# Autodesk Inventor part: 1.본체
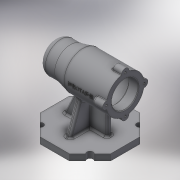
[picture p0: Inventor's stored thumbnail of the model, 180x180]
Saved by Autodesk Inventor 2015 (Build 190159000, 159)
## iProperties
Created: 2019-12
Part Number: 1.본체
Material: 일반
Document SubType Name: Modeling
Designer: SCD-A02
Density: 1 g/cm^3
Appearance: 기본값
Author: SCD-A02
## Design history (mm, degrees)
sketch "스케치1"
  geometry: L1 (0, 0)-(0, 25); L2 (0, 25)-(25, 25); L3 (25, 25)-(45, 30); L4 (45, 30)-(112, 30); L5 (112, 30)-(112, 0); L6 (112, 0)-(0, 0)
  constraints: 12 end point, 2 perpendicular, 2 vertical, 1 parallel
  dimensions: "d0" = 50 diameter of L2 L6; "d1" = 60 diameter of L4 L6; "d2" = 25 distance of L1.end L2.end; "d3" = 45 horizontal distance of L1.end L3.end; "d4" = 112 distance between parallel lines of L1 L5
revolve "회전1" sketch "스케치1" stored, may be unused: angle "d5" = 90 deg
sketch "스케치2"
  geometry: L1 (6, 0)-(9, 0); L2 (9, 0)-(9, 10.5); L3 (9, 10.5)-(6, 10.5); L4 (6, 10.5)-(6, 0); L5 (9, 0)-(13, 0); L6 (13, 0)-(13, 16); L7 (13, 16)-(9, 16); L8 (9, 16)-(9, 0); L9 (13, 0)-(31, 0); L10 (31, 0)-(31, 17.5); L11 (31, 17.5)-(13, 17.5); L12 (13, 17.5)-(13, 0); L13 (31, 0)-(43, 0); L14 (43, 0)-(43, 21); L15 (43, 21)-(31, 21); L16 (31, 21)-(31, 0); L17 (43, 0)-(97, 0); L18 (97, 0)-(97, 24); L19 (97, 24)-(43, 24); L20 (43, 24)-(43, 0); L21 (112, -30)-(112, 30) reference; L22 (97, 0)-(112, 0); L23 (112, 0)-(112, 21); L24 (112, 21)-(97, 21); L25 (97, 21)-(97, 0); 1 further point
  constraints: 48 end point, 12 parallel, 6 horizontal, 6 perpendicular, 1 point on line
  dimensions: "d6" = 0 vertical distance of point (0, 0) L1.start; "d7" = 3 distance of L2.end L3.end; "d8" = 4 distance of L6.end L7.end; "d9" = 18 distance of L10.end L11.end; "d10" = 12 distance of L14.end L15.end; "d11" = 42 diameter of L15 L13; "d12" = 48 diameter of L19 L17; "d13" = 15 distance between parallel lines of L23 L25; "d14" = 54 distance between parallel lines of L25 L14; "d15" = 42 diameter of L24 L22; "d16" = 35 diameter of L11 L9; "d17" = 21 diameter of L3 L1; "d18" = 32 diameter of L7 L5
revolve "회전2" stored, may be unused: angle "d19" = 90 deg
node "작업 평면1"
sketch "스케치3"
  geometry: L1 (56, 0)-(5.263, 50.737); L2 (56, 0)-(0, 0); L3 (16.402, 39.598)-(0, 23.196); L4 (0, 23.196)-(16.402, 39.598); L5 (16.402, 39.598)-(32.804, 56); L6 (56, 56)-(32.804, 56); L7 (0, 0)-(0, 23.196); L8 (56, 0)-(95.901, 39.901); L9 (112, 0)-(112, 23.196); L10 (56, 56)-(79.196, 56); L11 (95.598, 39.598)-(79.196, 56); L12 (95.598, 39.598)-(112, 23.196); L13 (0, 0)-(0, -23.196); L14 (16.402, -39.598)-(0, -23.196); L15 (16.402, -39.598)-(32.804, -56); L16 (56, -56)-(32.804, -56); L17 (56, -56)-(79.196, -56); L18 (95.598, -39.598)-(79.196, -56); L19 (95.598, -39.598)-(112, -23.196); L20 (112, 0)-(112, -23.196); A1 r 56 centre (56, 0) between (16.402, 39.598) and (0, 0)
  constraints: 40 end point, 7 symmetric about line, 6 tangent, 3 horizontal, 3 point on line, 2 perpendicular, 2 point on circle, 2 vertical, 1 centre point, 1 collinear
  dimensions: "d21" = 56 distance of L1.start L2.end; "d22" = 112 diameter of A1; "d23" = 45 deg angle of L1 L2; "d24" = 45 deg angle of L8 L2
extrude "돌출1" join sketch "스케치3" distance "d25" = 10; taper "d26" = 0 deg
sketch "스케치4"
  geometry: L1 (-32.804, -70)-(0, -70) reference; L2 (-18, -70)-(-40.099, -22.609); L3 (-40.099, -22.609)-(-87, -22.609); L4 (-112, -70)-(-79.196, -70) reference; L5 (-79.196, -70)-(-32.804, -70) reference; L6 (0, -80)-(0, -70) reference; L7 (-87, -22.609)-(-87, -70); L8 (-18, -70)-(-87, -70); L9 (-112, -80)-(-112, -70) reference; 1 further point
  constraints: 8 end point, 1 collinear, 1 horizontal, 1 point on line, 1 vertical
  dimensions: "d27" = 18 distance from line of L2.start L6; "d28" = 25 distance between parallel lines of L7 L9; "d62" = 115 deg angle of L2 L1
extrude "돌출2" join sketch "스케치4" stored distance "d29" = 8; taper "d30" = 0 deg
node "작업 평면2"
sketch "스케치5"
  geometry: L1 (70, -36)-(0, -10.522); L2 (0, -10.522)-(0, 0); L3 (0, 0)-(70, 0); L4 (27.875, -4)-(70, -4) reference; L5 (70, 0)-(70, -36); L6 (70, -56)-(70, -23.196) reference; L7 (80, -56)-(70, -56) reference; L8 (70, 36)-(0, 10.522); L9 (0, 10.522)-(0, 0); L10 (27.875, 4)-(70, 4); L11 (70, 0)-(70, 36); 1 further point
  constraints: 16 end point, 5 symmetric about line, 1 parallel, 1 perpendicular, 1 vertical
  dimensions: "d32" = 0 distance between parallel lines of L5 L6; "d33" = 20 distance from line of L1.start L7; "d34" = 110 deg angle of L1 L6
extrude "돌출3" join sketch "스케치5" stored distance "d35" = 8; taper "d36" = 0 deg
revolve "회전3" stored, may be unused: angle "d37" = 90 deg
sketch "스케치6"
  geometry: C1 r 21 at (0, 0) reference; C2 r 6 at (-30, 0); A1 r 30 centre (0, 0) between (29.732, 4) and (29.732, -4) reference; A2 r 30 centre (0, 0) between (29.732, 4) and (29.732, -4) reference
  constraints: 2 point on circle, 1 centre point, 1 horizontal alignment
  dimensions: "d38" = 12 diameter of C2
extrude "돌출4" join sketch "스케치6" distance "d39" = 16; taper "d40" = 0 deg
fillet "모깎기1" dims "d41" = 3
fillet "모깎기2" dims "d42" = 1
sketch "스케치7"
  geometry: A1 r 6 centre (0, 0) between (-0.171, 5.998) and (-0.171, -5.998) reference
hole "구멍1" sketch "스케치7" at (0, 0) diameter "d43" = 3.242; stored, may be unused: countersink angle "d47" = 90 deg, drill point angle "d49" = 118 deg; dims "d44" = 8, "d45" = 4, "d46" = 2, "d48" = 11
sketch "스케치8"
  geometry: L1 (32.804, 56)-(0, 23.196) reference; C1 r 5 at (16.402, 39.598); 1 further point
  constraints: 1 centre point, 1 midpoint
  dimensions: "d53" = 10 diameter of C1
extrude "돌출5" cut sketch "스케치8" stored distance "d54" = 16; taper "d55" = 0 deg
fillet "모깎기3" dims "d56" = 10, "d57" = 3, "d58" = 0.3
chamfer "모따기1" distance "d59" = 1; stored, may be unused: second distance "d60" = 2, angle "d61" = 45 deg
fillet "모깎기4" dims "d63" = 3
node "작업 평면3"
sketch "스케치9"
  geometry: L1 (-33.5, 29.226)-(-33.5, 6.771) reference; 2 further points
  constraints: 1 horizontal alignment, 1 other
  dimensions: "d64" = 41 distance from line of point (7.5, 0) L1
feature "엠보싱1" sketch "스케치9" dims "d65" = 0.5, "d66" = 0
node "솔리드1"
pattern_circular "원형 패턴1" dims "d51" = 360 deg
mirror "대칭1"
mirror "대칭2"
other parameters: "d31" = -56
